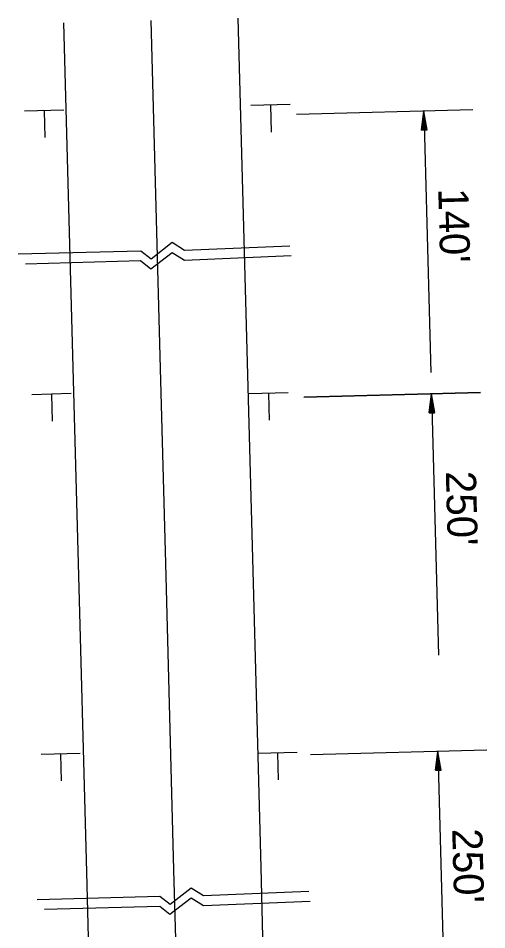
# Model space of a CAD drawing. Extents: x 1929624 to 1936506, y 596315 to 605721.
# Drawn here: x 1930186.6 to 1930282.3, y 599106.9 to 599293.2 of the extents above; entities that cross this region are included whole.
import ezdxf

# ---------------------------------------------------------------- set-up
doc = ezdxf.new("R2010")
doc.units = 0
doc.layers.add('Default', color=7, linetype='Continuous')

msp = doc.modelspace()

# ---------------------------------------------------------------- linework, layer by layer
at = {"layer": 'Default'}
for p, q in [((1930213.68, 599292.69), (1930215.59, 599221.56)), ((1930231.46, 599293.16), (1930233.35, 599222.81)), ((1930195.89, 599292.21), (1930197.78, 599221.8)), ((1930187.91, 599274.24), (1930195.92, 599274.46)), ((1930191.9, 599274.23), (1930192.04, 599268.77)), ((1930234.13, 599275.39), (1930242.13, 599275.6)), ((1930238.12, 599275.37), (1930238.26, 599269.91)), ((1930279.41, 599274.44), (1930243.4, 599273.47)), ((1930279.43, 599274.47), (1930243.42, 599273.51)), ((1930268.93, 599270.31), (1930269.4, 599274.17)), ((1930268.95, 599270.35), (1930269.42, 599274.2)), ((1930270.08, 599270.35), (1930269.4, 599274.17)), ((1930269.4, 599274.17), (1930270.83, 599220.78)), ((1930270.1, 599270.38), (1930269.42, 599274.2)), ((1930269.02, 599270.32), (1930269.42, 599273.53)), ((1930269.04, 599270.36), (1930269.44, 599273.56)), ((1930269.12, 599270.32), (1930269.43, 599272.87)), ((1930269.14, 599270.36), (1930269.45, 599272.9)), ((1930269.22, 599270.32), (1930269.45, 599272.23)), ((1930269.24, 599270.36), (1930269.47, 599272.27)), ((1930269.98, 599270.34), (1930269.42, 599273.53)), ((1930269.88, 599270.34), (1930269.43, 599272.87)), ((1930270, 599270.38), (1930269.44, 599273.56)), ((1930269.9, 599270.38), (1930269.45, 599272.9)), ((1930269.79, 599270.34), (1930269.45, 599272.23)), ((1930269.81, 599270.38), (1930269.47, 599272.27)), ((1930268.93, 599270.31), (1930270.08, 599270.35)), ((1930268.95, 599270.35), (1930270.1, 599270.38)), ((1930269.32, 599270.33), (1930269.47, 599271.58)), ((1930269.33, 599270.36), (1930269.49, 599271.62)), ((1930269.41, 599270.33), (1930269.49, 599270.94)), ((1930269.43, 599270.37), (1930269.5, 599270.98)), ((1930269.69, 599270.34), (1930269.47, 599271.58)), ((1930269.71, 599270.37), (1930269.49, 599271.62)), ((1930269.59, 599270.33), (1930269.49, 599270.94)), ((1930269.61, 599270.37), (1930269.5, 599270.98)), ((1930197.78, 599221.8), (1930198.72, 599186.77)), ((1930233.35, 599222.81), (1930234.29, 599187.78)), ((1930215.59, 599221.56), (1930216.66, 599181.74)), ((1930189.42, 599216.31), (1930197.42, 599216.53)), ((1930193.41, 599216.3), (1930193.55, 599210.84)), ((1930233.7, 599216.51), (1930241.7, 599216.72)), ((1930237.68, 599216.5), (1930237.83, 599211.04)), ((1930280.97, 599216.64), (1930244.95, 599215.68)), ((1930280.98, 599216.68), (1930244.97, 599215.72)), ((1930270.48, 599212.52), (1930270.95, 599216.37)), ((1930270.5, 599212.56), (1930270.97, 599216.41)), ((1930271.63, 599212.55), (1930270.95, 599216.37)), ((1930270.95, 599216.37), (1930272.38, 599162.99)), ((1930271.65, 599212.59), (1930270.97, 599216.41)), ((1930270.57, 599212.53), (1930270.97, 599215.73)), ((1930270.59, 599212.56), (1930270.99, 599215.77)), ((1930270.67, 599212.53), (1930270.99, 599215.07)), ((1930270.69, 599212.57), (1930271, 599215.11)), ((1930270.77, 599212.53), (1930271, 599214.44)), ((1930270.79, 599212.57), (1930271.02, 599214.47)), ((1930271.53, 599212.55), (1930270.97, 599215.73)), ((1930271.55, 599212.59), (1930270.99, 599215.77)), ((1930271.44, 599212.55), (1930270.99, 599215.07)), ((1930271.45, 599212.59), (1930271, 599215.11)), ((1930271.34, 599212.55), (1930271, 599214.44)), ((1930271.36, 599212.59), (1930271.02, 599214.47)), ((1930270.48, 599212.52), (1930271.63, 599212.55)), ((1930270.5, 599212.56), (1930271.65, 599212.59)), ((1930270.87, 599212.53), (1930271.02, 599213.79)), ((1930270.89, 599212.57), (1930271.04, 599213.82)), ((1930270.96, 599212.54), (1930271.04, 599213.15)), ((1930270.98, 599212.58), (1930271.06, 599213.18)), ((1930271.24, 599212.54), (1930271.02, 599213.79)), ((1930271.26, 599212.58), (1930271.04, 599213.82)), ((1930271.14, 599212.54), (1930271.04, 599213.15)), ((1930271.16, 599212.58), (1930271.06, 599213.18)), ((1930198.72, 599186.77), (1930200.55, 599118.68)), ((1930234.29, 599187.78), (1930236.12, 599119.64)), ((1930216.66, 599181.74), (1930218.34, 599119.16)), ((1930282.26, 599143.61), (1930246.25, 599142.64)), ((1930191.28, 599142.79), (1930199.28, 599143)), ((1930195.26, 599142.78), (1930195.41, 599137.31)), ((1930235.55, 599142.99), (1930243.56, 599143.2)), ((1930239.54, 599142.97), (1930239.69, 599137.51)), ((1930271.78, 599139.49), (1930272.25, 599143.34)), ((1930271.87, 599139.49), (1930272.27, 599142.7)), ((1930271.97, 599139.49), (1930272.28, 599142.04)), ((1930272.25, 599143.34), (1930273.68, 599089.95)), ((1930272.93, 599139.52), (1930272.25, 599143.34)), ((1930272.83, 599139.51), (1930272.27, 599142.7)), ((1930272.73, 599139.51), (1930272.28, 599142.04)), ((1930272.07, 599139.49), (1930272.3, 599141.4)), ((1930272.17, 599139.5), (1930272.32, 599140.75)), ((1930272.26, 599139.5), (1930272.34, 599140.11)), ((1930272.64, 599139.51), (1930272.3, 599141.4)), ((1930272.54, 599139.51), (1930272.32, 599140.75)), ((1930272.44, 599139.5), (1930272.34, 599140.11)), ((1930271.78, 599139.49), (1930272.93, 599139.52)), ((1930218.34, 599119.16), (1930220.23, 599048.58)), ((1930236.12, 599119.64), (1930238.01, 599049.05)), ((1930200.55, 599118.68), (1930202.45, 599048.1))]:
    msp.add_line(p, q, dxfattribs=at)
for points in [[(1930242.09, 599246.62), (1930220.58, 599245.71), (1930218.07, 599247.31), (1930213.73, 599243.95), (1930211.64, 599245.6), (1930186.62, 599244.94)], [(1930242.34, 599244.58), (1930220.55, 599243.67), (1930218.04, 599245.26), (1930213.7, 599241.91), (1930211.6, 599243.56), (1930188.11, 599242.93)], [(1930245.97, 599114.73), (1930224.46, 599113.83), (1930221.95, 599115.42), (1930217.61, 599112.07), (1930215.52, 599113.72), (1930190.5, 599113.05)], [(1930246.22, 599112.7), (1930224.43, 599111.78), (1930221.92, 599113.38), (1930217.58, 599110.02), (1930215.49, 599111.67), (1930191.99, 599111.04)]]:
    msp.add_lwpolyline(points, dxfattribs=at)

# ---------------------------------------------------------------- texts
for s, p in [("140'", (1930272.35, 599258.35)), ("250'", (1930273.9, 599200.56)), ("250'", (1930275.2, 599127.52))]:
    msp.add_text(s, height=6.14, rotation=271.5377, dxfattribs=at).set_placement(p)

doc.saveas('drawing.dxf')
